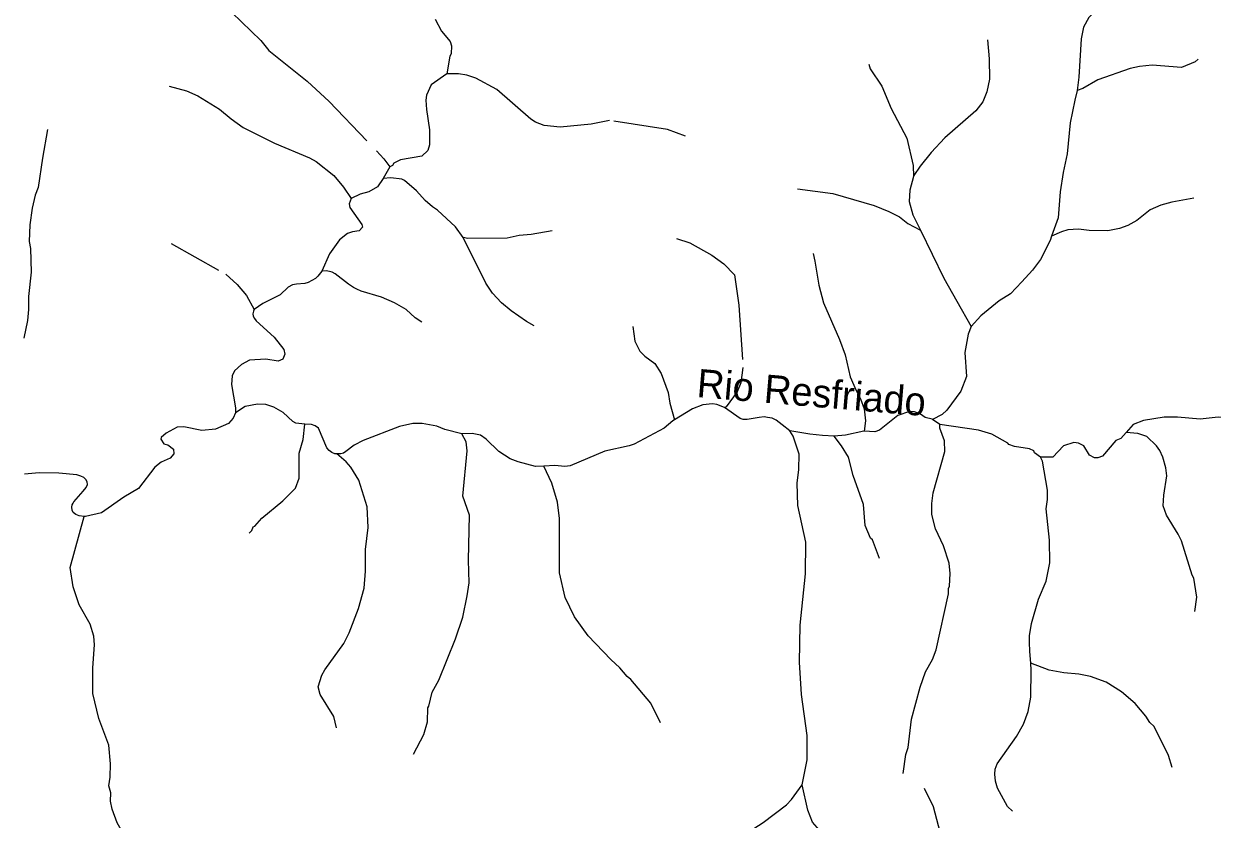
# Model space of a CAD drawing. Extents: x 280.4 to 335.6, y 8893.9 to 8949.5.
# Drawn here: x 280.57 to 288.97, y 8923.61 to 8929.23 of the extents above; entities that cross this region are included whole.
import ezdxf
from ezdxf.enums import TextEntityAlignment as Align

# ---------------------------------------------------------------- set-up
doc = ezdxf.new("R2010")
doc.units = 0
doc.header["$LTSCALE"] = 0.064
doc.linetypes.add('LONG_DASHED', pattern=[7.5, 6, -1.5])
doc.layers.add('61', color=7, linetype='Continuous')
doc.layers.add('7', color=7, linetype='Continuous', lineweight=25)
doc.layers.add('9', color=7, linetype='LONG_DASHED', lineweight=25)

msp = doc.modelspace()

# ---------------------------------------------------------------- linework, layer by layer
at = {"layer": '7'}
for p, q in [((283.1545, 8928.2173), (283.1074, 8928.1333)), ((287.0401, 8926.3961), (286.9898, 8926.4324))]:
    msp.add_line(p, q, dxfattribs=at)
for points in [[(283.4743, 8929.2592), (283.519, 8929.1736), (283.5799, 8929.1009), (283.5897, 8929.0705), (283.588, 8929.0154), (283.5784, 8928.9979), (283.5574, 8928.8737)], [(283.5574, 8928.8737), (283.446, 8928.7951), (283.4137, 8928.7228), (283.409, 8928.6883), (283.4134, 8928.6209), (283.4361, 8928.4765), (283.4361, 8928.3724), (283.4237, 8928.331), (283.3808, 8928.2909), (283.229, 8928.2646), (283.1838, 8928.2414), (283.173, 8928.226), (283.1545, 8928.2173)], [(283.1074, 8928.1333), (283.0666, 8928.0761), (283.0074, 8928.0406), (282.9456, 8928.023), (282.8804, 8927.9926)], [(282.8804, 8927.9926), (282.8677, 8927.9559), (282.8732, 8927.928), (282.9563, 8927.8085), (282.9621, 8927.7906), (282.9371, 8927.7642), (282.89, 8927.7576), (282.8566, 8927.7443), (282.7997, 8927.7), (282.7293, 8927.6008), (282.6736, 8927.4792)], [(282.6736, 8927.4792), (282.6464, 8927.4432), (282.6296, 8927.4269), (282.5772, 8927.3995), (282.5538, 8927.3925), (282.495, 8927.3879), (282.4669, 8927.3821), (282.4363, 8927.3664), (282.3799, 8927.3127), (282.2566, 8927.251), (282.1973, 8927.2084)], [(282.1973, 8927.2084), (282.1908, 8927.1963), (282.1871, 8927.1789), (282.1899, 8927.1616), (282.1981, 8927.1461), (282.2098, 8927.1295), (282.3374, 8927.0123), (282.4056, 8926.9267), (282.4139, 8926.8942), (282.399, 8926.8585), (282.3656, 8926.8447), (282.2782, 8926.8571), (282.1632, 8926.8506), (282.1056, 8926.8204), (282.0581, 8926.7761), (282.041, 8926.7408), (282.0352, 8926.6797), (282.0651, 8926.5137), (282.0652, 8926.4783)], [(282.5531, 8926.3985), (282.4915, 8926.4048), (282.4696, 8926.4179), (282.4014, 8926.4813), (282.3351, 8926.5184), (282.2775, 8926.5374), (282.2192, 8926.5403), (282.1337, 8926.5226), (282.0652, 8926.4783)], [(285.5188, 8926.5159), (285.4659, 8926.5372), (285.4335, 8926.5435), (285.3656, 8926.5342), (285.2938, 8926.5065), (285.1665, 8926.4285)], [(285.9796, 8926.352), (285.9257, 8926.3948), (285.8841, 8926.4263), (285.8551, 8926.4402), (285.8229, 8926.4459), (285.7985, 8926.4503), (285.7647, 8926.4461), (285.6788, 8926.4314), (285.6505, 8926.4319), (285.631, 8926.439), (285.5188, 8926.5159)], [(286.9898, 8926.4324), (286.9875, 8926.434), (286.9379, 8926.4468), (286.9048, 8926.4694), (286.8608, 8926.4865), (286.8259, 8926.4891), (286.7441, 8926.4593), (286.6147, 8926.3568), (286.5819, 8926.3444), (286.505, 8926.3484)], [(289.4097, 8926.5143), (289.3875, 8926.516), (289.3551, 8926.516), (289.3247, 8926.5083), (289.2928, 8926.4989), (289.1981, 8926.4454), (289.1528, 8926.4334), (289.0076, 8926.4476), (288.8794, 8926.4333), (288.7203, 8926.4479), (288.6253, 8926.4494), (288.4787, 8926.4257), (288.4061, 8926.3959), (288.3566, 8926.3407)], [(282.0652, 8926.4783), (282.0467, 8926.441), (282.0137, 8926.404), (281.9239, 8926.3633), (281.8266, 8926.3536), (281.6986, 8926.3805), (281.652, 8926.3774), (281.5753, 8926.3362), (281.5385, 8926.304), (281.5365, 8926.2932), (281.5572, 8926.2588), (281.5869, 8926.252), (281.6257, 8926.2213), (281.6277, 8926.1886), (281.6036, 8926.1589), (281.5381, 8926.1302), (281.4935, 8926.0947), (281.3779, 8925.9447), (281.2765, 8925.8828), (281.1165, 8925.7727), (281.0034, 8925.746), (280.9954, 8925.7471)], [(282.7812, 8926.1896), (282.766, 8926.1904), (282.7442, 8926.1997), (282.7259, 8926.2131), (282.7099, 8926.2327), (282.6496, 8926.3703), (282.6279, 8926.3878), (282.6024, 8926.3958), (282.5531, 8926.3985)], [(283.6633, 8926.3313), (283.5442, 8926.3603), (283.4871, 8926.3842), (283.3834, 8926.4029), (283.3162, 8926.4028), (283.2226, 8926.3824), (282.9666, 8926.2833), (282.9027, 8926.2497), (282.8444, 8926.2047), (282.8282, 8926.1949), (282.8081, 8926.1881), (282.7812, 8926.1896)], [(285.1665, 8926.4285), (285.1553, 8926.4216), (285.093, 8926.3701), (284.8821, 8926.2579), (284.845, 8926.2451), (284.6732, 8926.2092), (284.4276, 8926.1056), (284.3908, 8926.1008), (284.3213, 8926.107), (284.2424, 8926.1027)], [(286.7824, 8923.9311), (286.8012, 8924.0655), (286.8169, 8924.1151), (286.8394, 8924.3159), (286.9006, 8924.5413), (286.9396, 8924.6504), (286.9883, 8924.7372), (287.0137, 8924.806), (287.1016, 8925.1994), (287.1019, 8925.2371), (287.1097, 8925.2547), (287.1143, 8925.3434), (287.1062, 8925.4177), (287.0659, 8925.5392), (287.0095, 8925.6604), (286.9834, 8925.7603), (286.9834, 8925.8384), (286.9928, 8925.9146), (287.0747, 8926.2065), (287.0742, 8926.2805), (287.041, 8926.371), (287.0401, 8926.3961)], [(287.7514, 8926.1667), (287.7084, 8926.1974), (287.7036, 8926.2097), (287.6741, 8926.2246), (287.5687, 8926.24), (287.5272, 8926.2553), (287.521, 8926.2643), (287.4071, 8926.3284), (287.3134, 8926.3564), (287.0401, 8926.3961)], [(283.3213, 8924.0685), (283.3947, 8924.2079), (283.4197, 8924.2953), (283.4234, 8924.3963), (283.4308, 8924.4071), (283.4546, 8924.506), (283.502, 8924.5917), (283.6197, 8924.8831), (283.6694, 8925.0349), (283.7021, 8925.1856), (283.7144, 8925.2787), (283.7113, 8925.4386), (283.7176, 8925.7568), (283.6698, 8925.8904), (283.6999, 8926.2094), (283.6934, 8926.2734), (283.6633, 8926.3313)], [(283.7951, 8926.3215), (283.7375, 8926.3325), (283.6633, 8926.3313)], [(284.2424, 8926.1027), (284.183, 8926.0994), (284.0603, 8926.132), (284.0048, 8926.1539), (283.9239, 8926.205), (283.8349, 8926.2921), (283.7951, 8926.3215)], [(286.0681, 8923.8523), (286.1037, 8924.0289), (286.1022, 8924.1992), (286.0622, 8924.4894), (286.0494, 8924.7173), (286.0526, 8924.9787), (286.0925, 8925.3427), (286.0941, 8925.5658), (286.0365, 8925.8232), (286.0334, 8925.9817), (286.0445, 8926.0783), (286.0461, 8926.1858), (286.0043, 8926.3135), (285.9796, 8926.352)], [(286.2935, 8926.3142), (286.2104, 8926.3193), (286.1214, 8926.3281), (285.9796, 8926.352)], [(286.505, 8926.3484), (286.5045, 8926.3484), (286.3746, 8926.3215), (286.2935, 8926.3142)], [(286.6144, 8925.451), (286.5641, 8925.5807), (286.5515, 8925.5946), (286.5137, 8925.6835), (286.5023, 8925.8306), (286.4282, 8926.0374), (286.3957, 8926.1662), (286.3464, 8926.2452), (286.2935, 8926.3142)], [(288.3566, 8926.3407), (288.3185, 8926.2982), (288.2845, 8926.2832), (288.1889, 8926.1729), (288.1578, 8926.1603), (288.1322, 8926.1599), (288.0985, 8926.1807), (288.0569, 8926.2453), (288.0196, 8926.2653), (287.9877, 8926.2701), (287.9152, 8926.2451), (287.8399, 8926.165), (287.7514, 8926.1667)], [(288.8432, 8925.0751), (288.8556, 8925.1765), (288.8351, 8925.3116), (288.8223, 8925.3328), (288.7478, 8925.5748), (288.7254, 8925.6229), (288.6422, 8925.7563), (288.6181, 8925.8218), (288.6224, 8925.8978), (288.6432, 8926.034), (288.6368, 8926.0911), (288.6166, 8926.1666), (288.5949, 8926.2131), (288.5702, 8926.2457), (288.5022, 8926.311), (288.4386, 8926.3326), (288.3566, 8926.3407)], [(282.7771, 8924.254), (282.7582, 8924.3345), (282.6629, 8924.4905), (282.6494, 8924.5435), (282.675, 8924.6262), (282.6953, 8924.6646), (282.8288, 8924.8493), (282.867, 8924.9243), (282.9339, 8925.0964), (282.9724, 8925.241), (282.9819, 8925.3594), (282.9821, 8925.513), (283.0012, 8925.6687), (282.9942, 8925.8157), (282.9358, 8926.004), (282.8785, 8926.0953), (282.8455, 8926.1332), (282.7812, 8926.1896)], [(287.6823, 8924.7107), (287.6773, 8924.7927), (287.6732, 8924.8589), (287.6745, 8924.9029), (287.6875, 8924.9904), (287.7382, 8925.1635), (287.7907, 8925.2908), (287.8181, 8925.4194), (287.8149, 8925.5786), (287.7927, 8925.8016), (287.8021, 8925.8672), (287.802, 8925.9329), (287.7668, 8926.1385), (287.7514, 8926.1667)], [(285.0661, 8924.2889), (284.9982, 8924.4285), (284.8583, 8924.5951), (284.8314, 8924.6159), (284.78, 8924.6785), (284.7165, 8924.7371), (284.5565, 8924.905), (284.4585, 8925.0388), (284.3928, 8925.1757), (284.3542, 8925.3497), (284.3541, 8925.7336), (284.3396, 8925.848), (284.2995, 8925.983), (284.2424, 8926.1027)], [(280.9165, 8925.8398), (280.9225, 8925.8493), (280.9876, 8925.9249), (281.0094, 8925.9504), (281.0177, 8925.9716), (281.0159, 8925.9925), (281.0077, 8926.0075), (280.9917, 8926.021), (280.9723, 8926.0314), (280.9435, 8926.0412), (280.8167, 8926.0529), (280.6773, 8926.0559), (280.574, 8926.0445)], [(280.9954, 8925.7471), (280.9591, 8925.7521), (280.9364, 8925.7617), (280.9181, 8925.7754), (280.9112, 8925.791), (280.9091, 8925.8119), (280.9111, 8925.8279), (280.9165, 8925.8398)], [(287.553, 8923.6655), (287.518, 8923.6986), (287.448, 8923.8278), (287.433, 8923.8778), (287.428, 8923.9264), (287.4314, 8923.9616), (287.4462, 8924.0005), (287.5823, 8924.1918), (287.6323, 8924.2788), (287.6643, 8924.3696), (287.6837, 8924.4702), (287.6853, 8924.6615), (287.6823, 8924.7107)], [(288.6812, 8923.9746), (288.6558, 8924.058), (288.5538, 8924.2637), (288.5248, 8924.2927), (288.4954, 8924.3371), (288.4204, 8924.4269), (288.3234, 8924.5078), (288.216, 8924.576), (288.1041, 8924.6162), (288.0236, 8924.6341), (287.9172, 8924.6423), (287.8125, 8924.6613), (287.6823, 8924.7107)], [(285.3795, 8923.1514), (285.4805, 8923.3118), (285.5493, 8923.3936), (285.6944, 8923.5227), (285.7934, 8923.5852), (285.957, 8923.7103), (285.9929, 8923.7477), (286.0681, 8923.8523)], [(286.4884, 8922.8963), (286.4998, 8922.9429), (286.4987, 8922.9917), (286.4747, 8923.1261), (286.46, 8923.1839), (286.4488, 8923.2373), (286.4425, 8923.2565), (286.3867, 8923.346), (286.3675, 8923.366), (286.2226, 8923.4934), (286.1417, 8923.5874), (286.1072, 8923.6723), (286.0681, 8923.8523)], [(286.9295, 8923.8274), (286.9929, 8923.6986), (287.0406, 8923.5202), (287.06, 8923.3621), (287.0645, 8923.2748)]]:
    msp.add_lwpolyline(points, dxfattribs=at)
at = {"layer": '9'}
for points in [[(281.6252, 8930.0258), (281.6897, 8929.9165), (281.7916, 8929.6939), (281.8432, 8929.6047), (281.8628, 8929.5543), (281.8709, 8929.5336), (281.9607, 8929.4039), (282.0378, 8929.3064), (282.2442, 8929.1094), (282.3008, 8929.0386), (282.5712, 8928.8222), (282.726, 8928.6772), (283.1133, 8928.2739), (283.1545, 8928.2173)], [(288.3395, 8929.8366), (288.352, 8929.7303), (288.3493, 8929.6365), (288.3296, 8929.5202), (288.3041, 8929.4656), (288.213, 8929.3762), (288.1463, 8929.3267), (288.0926, 8929.2714), (288.055, 8929.2016), (288.0388, 8929.1209), (288.0229, 8928.8489), (288.0107, 8928.7558)], [(287.3765, 8929.1121), (287.3891, 8928.9782), (287.3914, 8928.8359), (287.373, 8928.7464), (287.3435, 8928.6762), (287.2944, 8928.6126), (287.0765, 8928.4216), (286.9797, 8928.3184), (286.901, 8928.2209), (286.8572, 8928.1547), (286.8556, 8928.1489)], [(286.5393, 8928.9413), (286.5493, 8928.9094), (286.6298, 8928.7858), (286.6974, 8928.6284), (286.8073, 8928.4196), (286.8521, 8928.2252), (286.8556, 8928.1489)], [(288.8656, 8928.9758), (288.8454, 8928.9574), (288.7482, 8928.9186), (288.5416, 8928.9344), (288.4504, 8928.925), (288.3851, 8928.9107), (288.1561, 8928.8308), (288.0503, 8928.7692), (288.0107, 8928.7558)], [(285.2427, 8928.4333), (285.1176, 8928.4788), (284.7066, 8928.5441), (284.5765, 8928.5171), (284.358, 8928.4965), (284.2447, 8928.5078), (284.1827, 8928.5327), (284.1517, 8928.5522), (283.9116, 8928.7631), (283.7623, 8928.8433), (283.6978, 8928.8627), (283.6401, 8928.8722), (283.5574, 8928.8737)], [(281.5963, 8928.7865), (281.7192, 8928.7521), (281.7991, 8928.7168), (281.9522, 8928.624), (282.0337, 8928.5544), (282.1195, 8928.4931), (282.3387, 8928.384), (282.5877, 8928.2807), (282.6339, 8928.2545), (282.7581, 8928.1556), (282.828, 8928.0716), (282.8804, 8927.9926)], [(288.0107, 8928.7558), (287.9947, 8928.688), (287.9623, 8928.5272), (287.9401, 8928.3074), (287.9108, 8928.1758), (287.8916, 8928.0398), (287.8756, 8927.8551), (287.8305, 8927.7273)], [(280.7363, 8928.4809), (280.7016, 8928.2781), (280.6707, 8928.0704), (280.6493, 8928.0166), (280.6277, 8927.9249), (280.6107, 8927.8062), (280.6055, 8927.6896), (280.615, 8927.6399), (280.6214, 8927.473), (280.6023, 8927.2999), (280.6022, 8927.209), (280.5943, 8927.1315), (280.5684, 8927.0057)], [(283.672, 8927.718), (283.6184, 8927.7926), (283.4926, 8927.9106), (283.4563, 8927.9333), (283.4048, 8927.9777), (283.3431, 8928.0457), (283.2577, 8928.1201), (283.2387, 8928.1294), (283.1626, 8928.1397), (283.1074, 8928.1333)], [(286.8556, 8928.1489), (286.8291, 8928.0525), (286.8227, 8927.9713), (286.8499, 8927.8776), (286.9037, 8927.768)], [(286.036, 8928.062), (286.2857, 8928.0289), (286.5763, 8927.9433), (286.681, 8927.9015), (286.7548, 8927.8629), (286.8148, 8927.8156), (286.9037, 8927.768)], [(288.8341, 8927.9942), (288.6801, 8927.9672), (288.6026, 8927.9459), (288.5272, 8927.913), (288.4332, 8927.8373), (288.3681, 8927.8024), (288.3106, 8927.7816), (288.2285, 8927.764), (288.0946, 8927.7672), (288.0212, 8927.7766), (287.9451, 8927.7703), (287.8996, 8927.7575), (287.8305, 8927.7273)], [(284.3012, 8927.7643), (284.1525, 8927.7386), (284.0678, 8927.7319), (283.9834, 8927.7128), (283.7056, 8927.7112), (283.672, 8927.718)], [(286.9037, 8927.768), (287.0697, 8927.4297), (287.1612, 8927.267), (287.2611, 8927.0895)], [(281.6099, 8927.674), (281.9967, 8927.4585), (282.0767, 8927.3849), (282.1425, 8927.3082), (282.1973, 8927.2084)], [(284.1741, 8927.0938), (284.121, 8927.1228), (284.0129, 8927.1983), (283.9445, 8927.2558), (283.8795, 8927.3237), (283.8324, 8927.395), (283.672, 8927.718)], [(285.1808, 8927.7101), (285.2753, 8927.6792), (285.4296, 8927.5922), (285.5142, 8927.5306), (285.5901, 8927.4535), (285.6207, 8927.2387), (285.6495, 8926.7996), (285.6352, 8926.69), (285.6082, 8926.626), (285.5311, 8926.5218), (285.5188, 8926.5159)], [(287.8305, 8927.7273), (287.8195, 8927.696), (287.7509, 8927.5624), (287.6953, 8927.4859), (287.6199, 8927.4052), (287.5404, 8927.32), (287.4599, 8927.2706), (287.3303, 8927.1637), (287.2611, 8927.0895)], [(286.1467, 8927.6046), (286.1565, 8927.5495), (286.1864, 8927.3814), (286.2194, 8927.2564), (286.3324, 8926.9963), (286.3709, 8926.8883), (286.4076, 8926.7323), (286.4484, 8926.6366), (286.4808, 8926.578), (286.5062, 8926.508), (286.5144, 8926.4222), (286.505, 8926.3484)], [(283.3806, 8927.1186), (283.3334, 8927.1504), (283.2704, 8927.2075), (283.1882, 8927.2554), (283.0955, 8927.2969), (282.9517, 8927.3375), (282.9223, 8927.3523), (282.8988, 8927.3639), (282.8615, 8927.3886), (282.7685, 8927.4596), (282.7484, 8927.4712), (282.7293, 8927.4769), (282.7049, 8927.4808), (282.6736, 8927.4792)], [(284.8714, 8927.0897), (284.885, 8926.9843), (284.9219, 8926.9148), (284.9566, 8926.8801), (285.0273, 8926.8283), (285.0724, 8926.7572), (285.1201, 8926.6222), (285.1318, 8926.5463), (285.1665, 8926.4285)], [(287.2611, 8927.0895), (287.241, 8927.0352), (287.217, 8926.9043), (287.2291, 8926.7364), (287.1899, 8926.6327), (287.0899, 8926.4984), (287.0571, 8926.4662), (286.9898, 8926.4324)], [(282.1616, 8925.6282), (282.1801, 8925.6487), (282.1887, 8925.6747), (282.2012, 8925.6789), (282.2501, 8925.7352), (282.3995, 8925.8576), (282.4876, 8925.9458), (282.5131, 8926.0176), (282.5135, 8926.1942), (282.542, 8926.2895), (282.5531, 8926.3985)], [(281.2941, 8923.467), (281.2278, 8923.5835), (281.194, 8923.6794), (281.1814, 8923.737), (281.1825, 8923.796), (281.1687, 8923.8436), (281.1779, 8923.9065), (281.1812, 8924), (281.1699, 8924.1321), (281.0991, 8924.319), (281.0567, 8924.4954), (281.0565, 8924.6767), (281.0675, 8924.8409), (281.0626, 8924.9013), (281.0381, 8924.9859), (280.96, 8925.1223), (280.9169, 8925.2507), (280.8969, 8925.3867), (280.9954, 8925.7471)]]:
    msp.add_lwpolyline(points, dxfattribs=at)

# ---------------------------------------------------------------- texts
at = {"layer": '61'}
msp.add_text('Rio Resfriado', height=0.2, rotation=355.236, dxfattribs=at).set_placement((286.1257, 8926.5233), align=Align.CENTER)

doc.saveas('drawing.dxf')
